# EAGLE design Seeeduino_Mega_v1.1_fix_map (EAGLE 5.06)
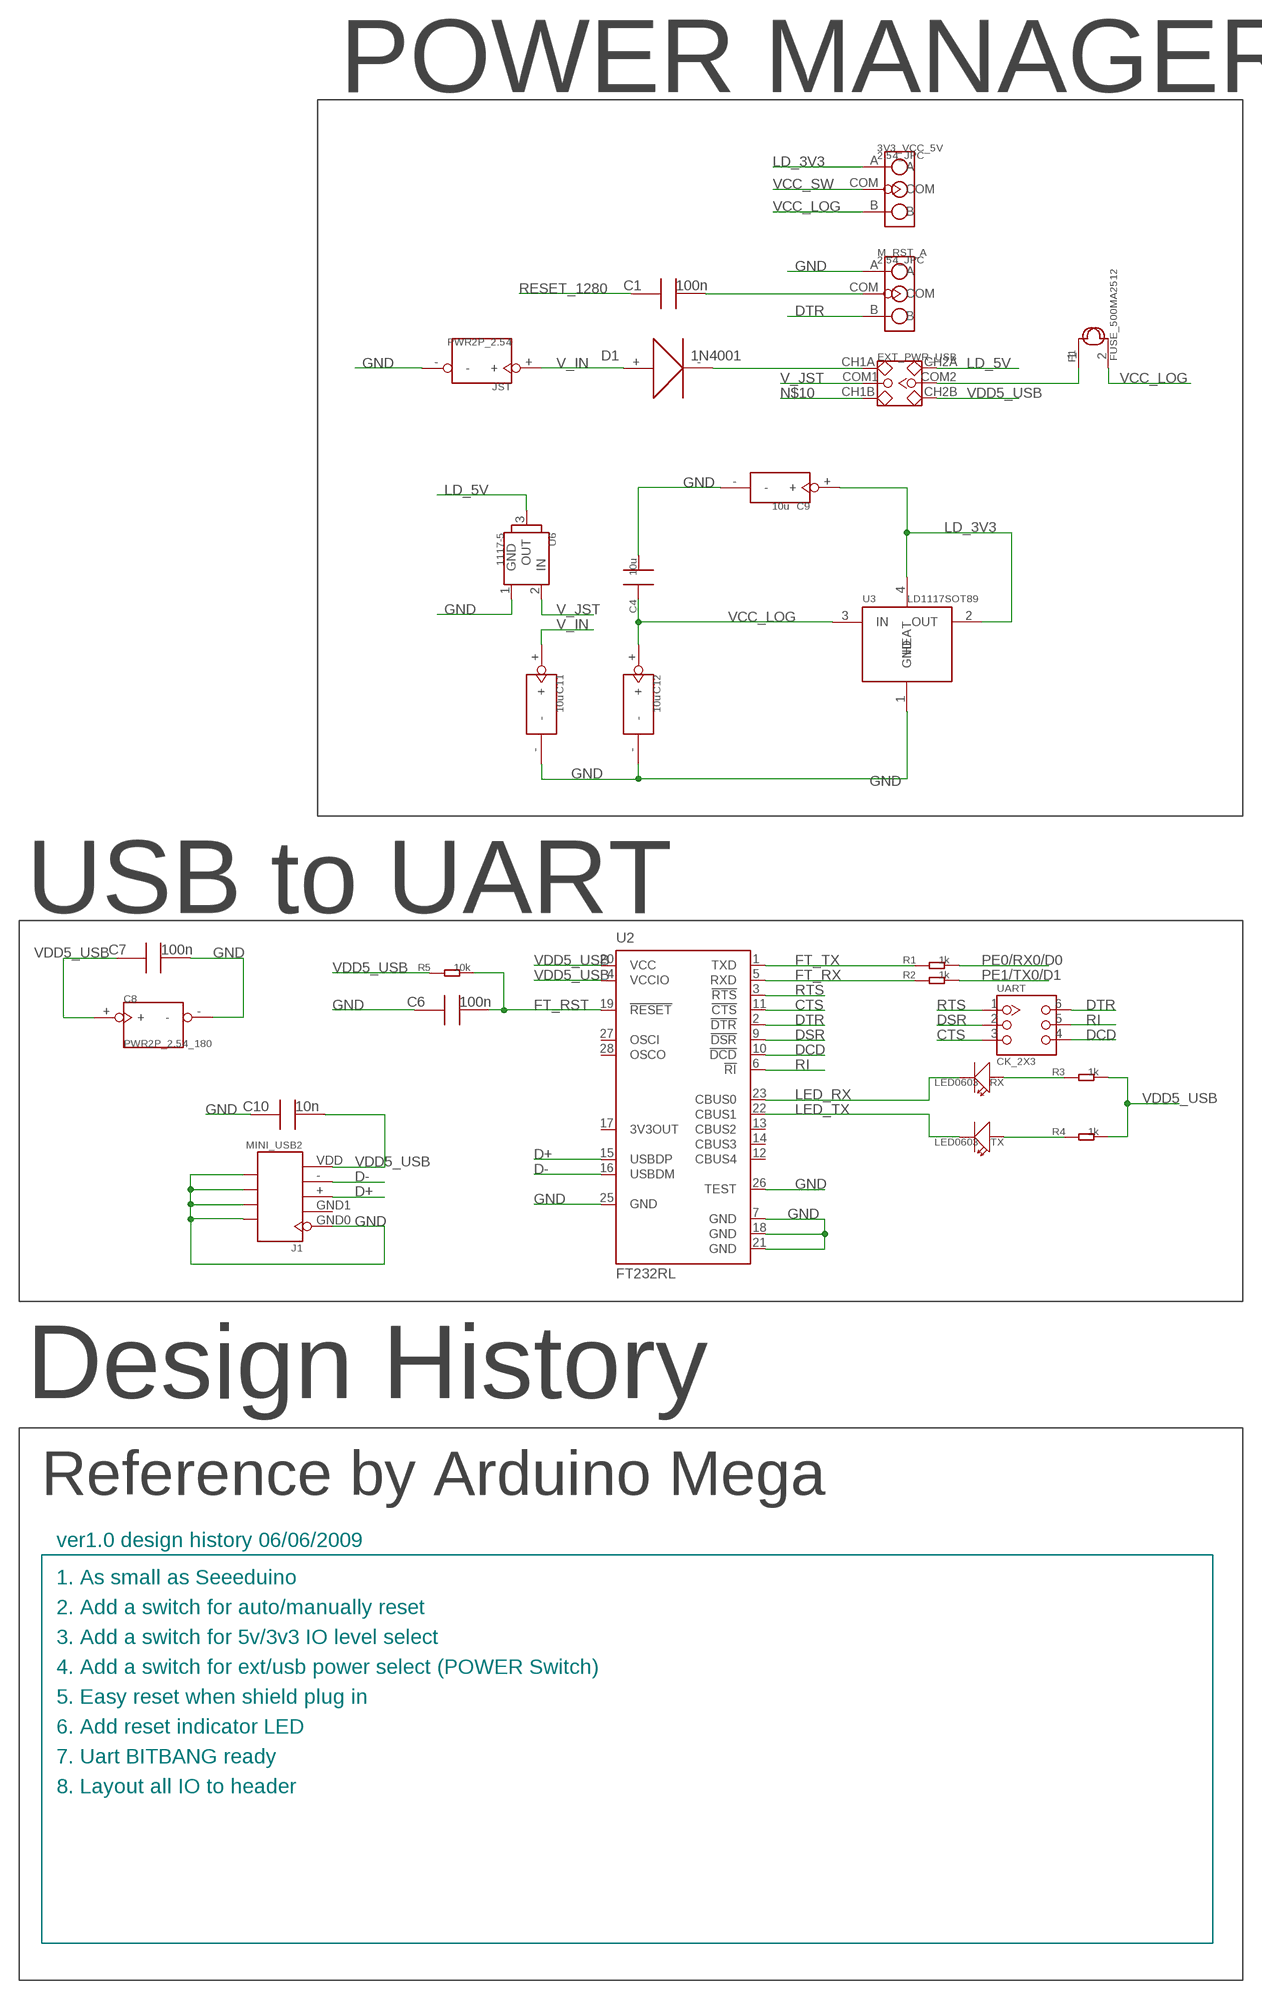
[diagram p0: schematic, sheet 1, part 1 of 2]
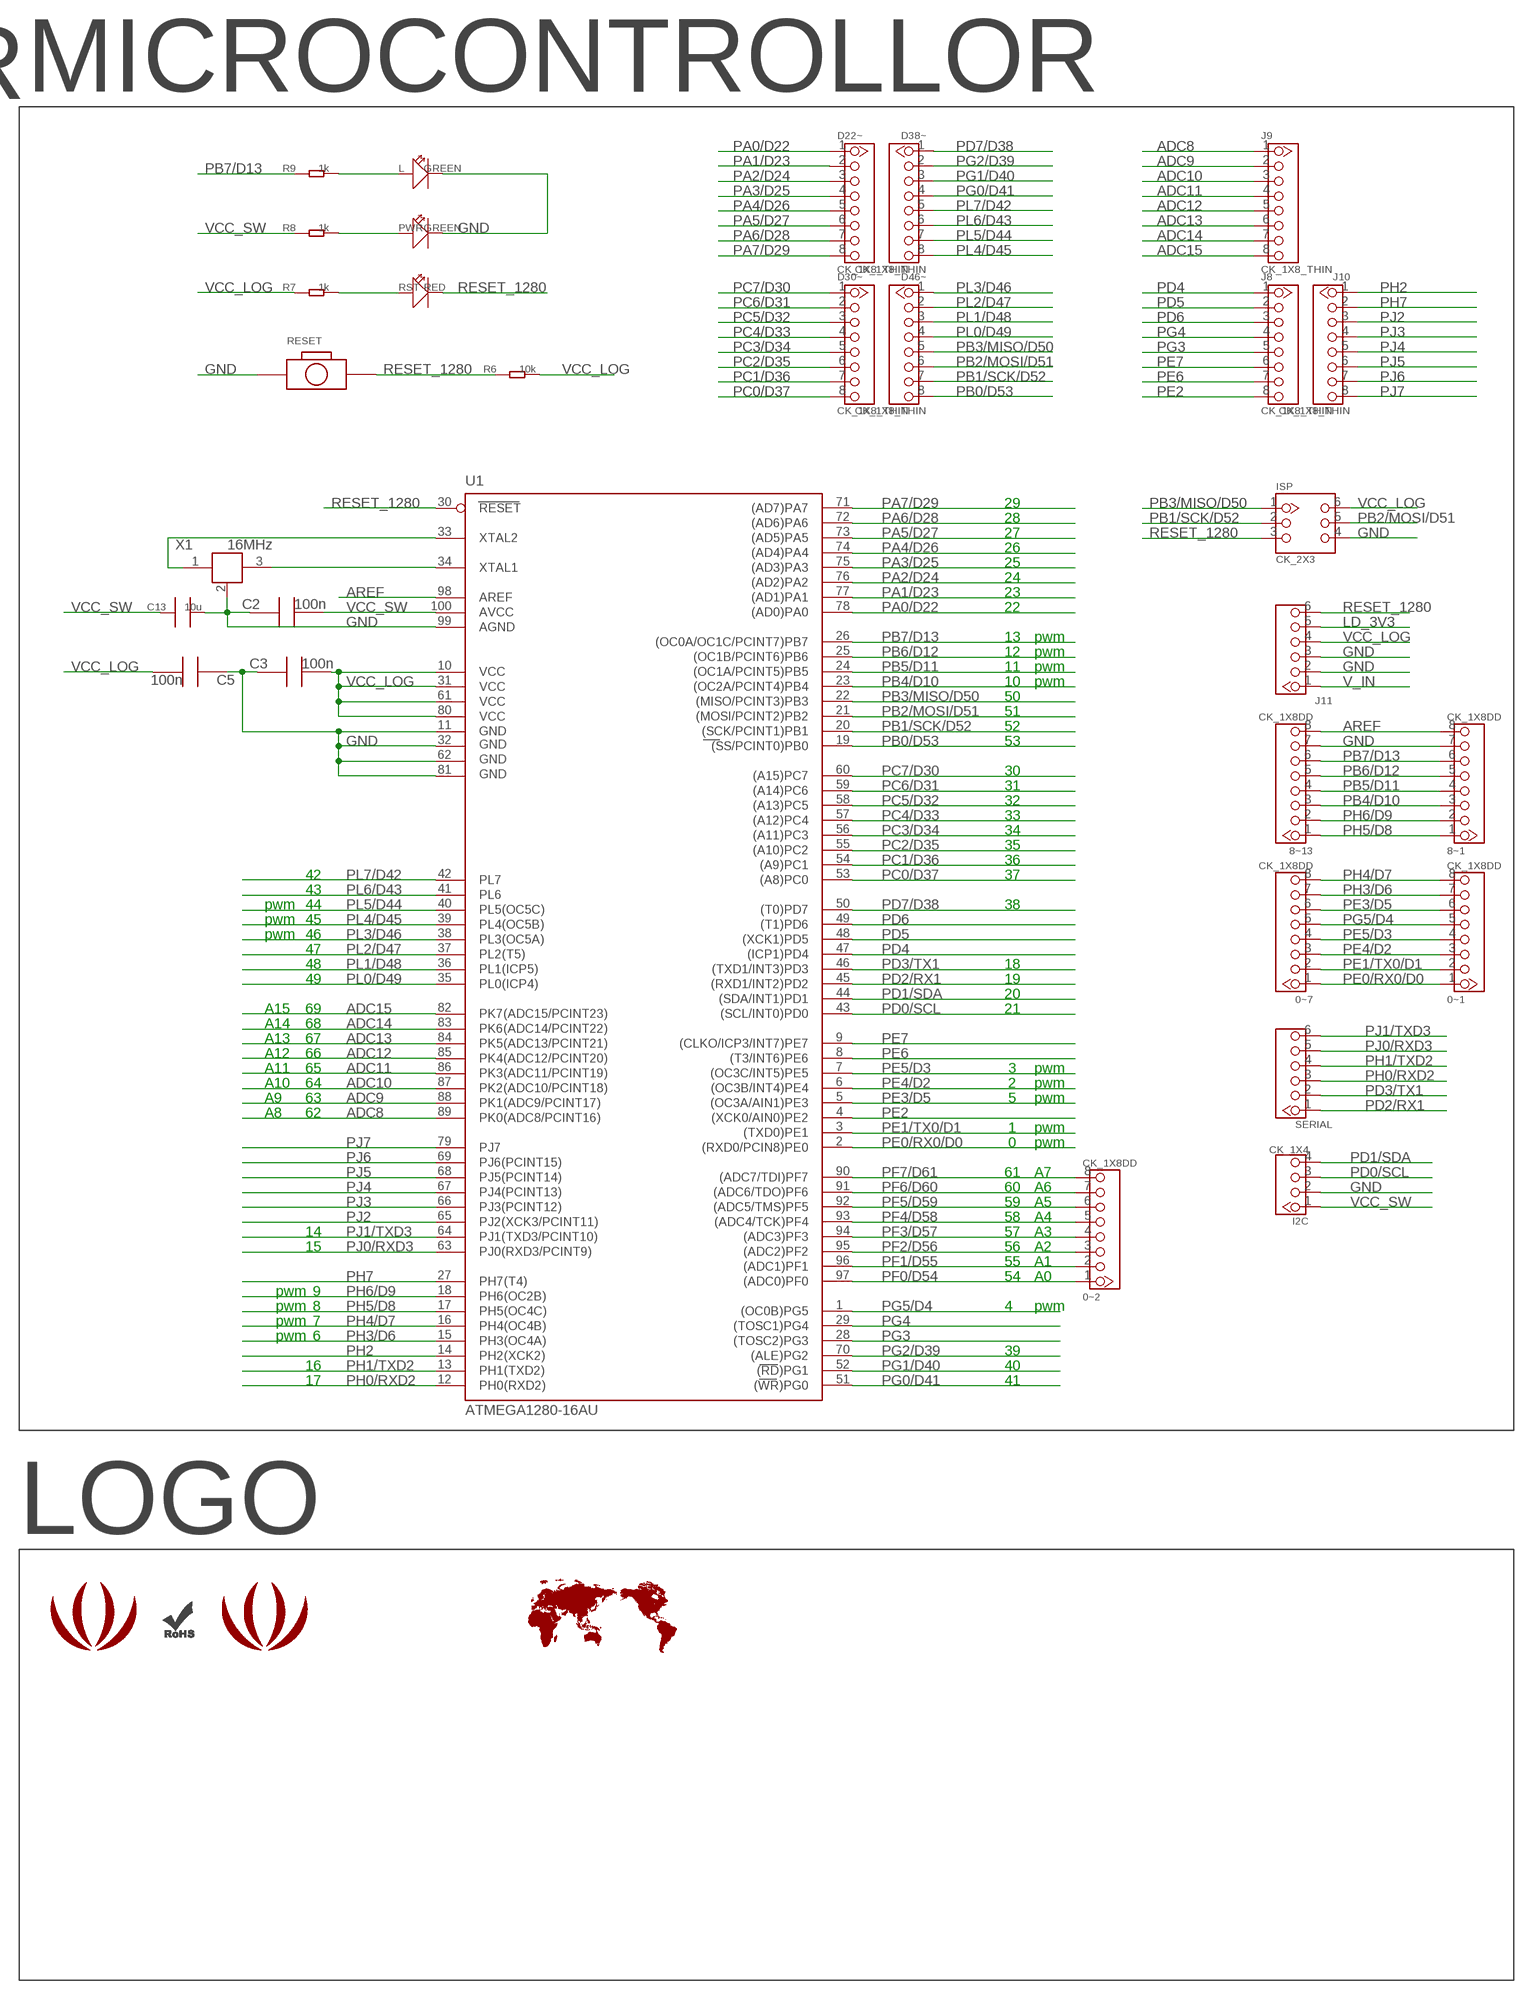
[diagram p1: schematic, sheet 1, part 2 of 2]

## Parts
0~1  CK_1X8DD  [CK_1X8]
0~2  CK_1X8DD  [CK_1X8]
0~7  CK_1X8DD  [CK_1X8]
3V3_VCC_5V  2.54_JPC  [2.54_JP_C]
8~1  CK_1X8DD  [CK_1X8]
8~13  CK_1X8DD  [CK_1X8]
C1  100n  C0603  [0603]
C2  100n  C0603  [0603]
C3  100n  C0603  [0603]
C4  10u  C0805  [0805]
C5  100n  C0603  [0603]
C6  100n  C0603  [0603]
C7  100n  C0603  [0603]
C8  PWR2P_2.54_180  [PWR_1X2]
C9  10u  C_TAN_3X3.5  [C_TAN_3X3.5]
C10  10n  C0603  [0603]
C11  10u  C_TAN_3X3.5  [C_TAN_3X3.5]
C12  10u  C_TAN_3X3.5  [C_TAN_3X3.5]
C13  10u  C0805  [0805]
D1  1N4001  DIODE2010  [DIODE_2010]
D22~  CK_1X8_THIN  [CK_1X8_THIN]
D30~  CK_1X8_THIN  [CK_1X8_THIN]
D38~  CK_1X8_THIN  [CK_1X8_THIN]
D46~  CK_1X8_THIN  [CK_1X8_THIN]
EXT_PWR_USB  2.54SW_2CH  [2.54SW_2CH]
F1  FUSE_500MA2512  [2512]
I2C  CK_1X4  [CK_1X4]
ISP  CK_2X3  [CK_2X3_THIN]
J1  MINI_USB2  [MINI_USB2]
J8  CK_1X8_THIN  [CK_1X8_THIN]
J9  CK_1X8_THIN  [CK_1X8_THIN]
J10  CK_1X8_THIN  [CK_1X8_THIN]
J11  CK_1X6  [CK_1X6]
JST  PWR2P_2.54  [PWR_JST]
L  GREEN  LED0603  [LED0603]
LOGO1  LOGO_SILK  [LOGO_SILK]
LOGO2  ROHSSILK  [ROHS_SILK]
LOGO3  LOGO_COPPER150X124  [LOGO_COPPER_150X124]
M_RST_A  2.54_JPC  [2.54_JP_C]
PWR  GREEN  LED0603  [LED0603]
R1  1k  R0603  [0603]
R2  1k  R0603  [0603]
R3  1k  R0603  [0603]
R4  1k  R0603  [0603]
R5  10k  R0603  [0603]
R6  10k  R0603  [0603]
R7  1k  R0603  [0603]
R8  1k  R0603  [0603]
R9  1k  R0603  [0603]
RESET  BOTTON_1_DP  [BTN_5.0_RST]
RST  RED  LED0603  [LED0603]
RX  LED0603  [LED0603]
SERIAL  CK_1X6  [CK_1X6]
TX  LED0603  [LED0603]
U1  ATMEGA1280-16AU  [TQFP100]
U2  FT232RL  [SSOP28]
U3  LD1117SOT89  [SOT89]
U6  1117-5  [TO252]
U$2  WORLD_MAP_IID  [WORLD_MAP_1000X500]
UART  CK_2X3  [CK_2X3_THIN]
X1  16MHz  XTAL_NC4X3  [XTAL_4X3]

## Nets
ADC8: J9.1 U1.89(PK0(ADC8/PCINT16))
ADC9: J9.2 U1.88(PK1(ADC9/PCINT17))
ADC10: J9.3 U1.87(PK2(ADC10/PCINT18))
ADC11: J9.4 U1.86(PK3(ADC11/PCINT19))
ADC12: J9.5 U1.85(PK4(ADC12/PCINT20))
ADC13: J9.6 U1.84(PK5(ADC13/PCINT21))
ADC14: J9.7 U1.83(PK6(ADC14/PCINT22))
ADC15: J9.8 U1.82(PK7(ADC15/PCINT23))
AREF: 8~1.8 8~13.8 U1.98(AREF)
CTS: U2.11(!CTS) UART.3
D+: J1.+ U2.15(USBDP)
D-: J1.- U2.16(USBDM)
DCD: U2.10(!DCD) UART.4
DSR: U2.9(!DSR) UART.2
DTR: M_RST_A.B U2.2(!DTR) UART.6
FT_RST: C6.2 R5.2 U2.19(!RESET)
FT_RX: R2.1 U2.5(RXD)
FT_TX: R1.1 U2.1(TXD)
GND: 8~1.7 8~13.7 C2.1 C3.1 C4.2 C5.1 C6.1 C7.2 C8.- C9.- C10.1 C11.- C12.- C13.2 I2C.2 ISP.4 J1.GND0 J1.P$6 J1.P$7 J1.P$8 J1.P$9 J11.2 J11.3 JST.- L.2(-) M_RST_A.A PWR.2(-) RESET.P$1 U1.11(GND) U1.32(GND1) U1.62(GND2) U1.81(GND3) U1.99(AGND) U2.7(GND) U2.18(GND) U2.21(GND) U2.25(GND) U2.26(TEST) U3.1(GND) U6.1(GND) X1.2(GND)
LD_3V3: 3V3_VCC_5V.A C9.+ J11.5 U3.2(OUT) U3.4(HEAT)
LD_5V: EXT_PWR_USB.CH2A U6.3(OUT)
LED_RX: RX.2(-) U2.23(CBUS0)
LED_TX: TX.2(-) U2.22(CBUS1)
N$1: EXT_PWR_USB.COM2 F1.1
N$2: U1.34(XTAL1) X1.3
N$3: U1.33(XTAL2) X1.1
N$5: R7.2 RST.1(+)
N$7: D1.- EXT_PWR_USB.CH1A
N$8: PWR.1(+) R8.2
N$9: L.1(+) R9.2
N$10: EXT_PWR_USB.CH1B
N$18: C1.2 M_RST_A.COM
N$31: R3.1 RX.1(+)
N$32: R4.1 TX.1(+)
PA0/D22: D22~.1 U1.78((AD0)PA0)
PA1/D23: D22~.2 U1.77((AD1)PA1)
PA2/D24: D22~.3 U1.76((AD2)PA2)
PA3/D25: D22~.4 U1.75((AD3)PA3)
PA4/D26: D22~.5 U1.74((AD4)PA4)
PA5/D27: D22~.6 U1.73((AD5)PA5)
PA6/D28: D22~.7 U1.72((AD6)PA6)
PA7/D29: D22~.8 U1.71((AD7)PA7)
PB0/D53: D46~.8 U1.19((SS/PCINT0)PB0)
PB1/SCK/D52: D46~.7 ISP.2 U1.20((SCK/PCINT1)PB1)
PB2/MOSI/D51: D46~.6 ISP.5 U1.21((MOSI/PCINT2)PB2)
PB3/MISO/D50: D46~.5 ISP.1 U1.22((MISO/PCINT3)PB3)
PB4/D10: 8~1.3 8~13.3 U1.23((OC2A/PCINT4)PB4)
PB5/D11: 8~1.4 8~13.4 U1.24((OC1A/PCINT5)PB5)
PB6/D12: 8~1.5 8~13.5 U1.25((OC1B/PCINT6)PB6)
PB7/D13: 8~1.6 8~13.6 R9.1 U1.26((OC0A/OC1C/PCINT7)PB7)
PC0/D37: D30~.8 U1.53((A8)PC0)
PC1/D36: D30~.7 U1.54((A9)PC1)
PC2/D35: D30~.6 U1.55((A10)PC2)
PC3/D34: D30~.5 U1.56((A11)PC3)
PC4/D33: D30~.4 U1.57((A12)PC4)
PC5/D32: D30~.3 U1.58((A13)PC5)
PC6/D31: D30~.2 U1.59((A14)PC6)
PC7/D30: D30~.1 U1.60((A15)PC7)
PD0/SCL: I2C.3 U1.43((SCL/INT0)PD0)
PD1/SDA: I2C.4 U1.44((SDA/INT1)PD1)
PD2/RX1: SERIAL.1 U1.45((RXD1/INT2)PD2)
PD3/TX1: SERIAL.2 U1.46((TXD1/INT3)PD3)
PD4: J8.1 U1.47((ICP1)PD4)
PD5: J8.2 U1.48((XCK1)PD5)
PD6: J8.3 U1.49((T1)PD6)
PD7/D38: D38~.1 U1.50((T0)PD7)
PE0/RX0/D0: 0~1.1 0~7.1 R1.2 U1.2((RXD0/PCIN8)PE0)
PE1/TX0/D1: 0~1.2 0~7.2 R2.2 U1.3((TXD0)PE1)
PE2: J8.8 U1.4((XCK0/AIN0)PE2)
PE3/D5: 0~1.6 0~7.6 U1.5((OC3A/AIN1)PE3)
PE4/D2: 0~1.3 0~7.3 U1.6((OC3B/INT4)PE4)
PE5/D3: 0~1.4 0~7.4 U1.7((OC3C/INT5)PE5)
PE6: J8.7 U1.8((T3/INT6)PE6)
PE7: J8.6 U1.9((CLKO/ICP3/INT7)PE7)
PF0/D54: 0~2.1 U1.97((ADC0)PF0)
PF1/D55: 0~2.2 U1.96((ADC1)PF1)
PF2/D56: 0~2.3 U1.95((ADC2)PF2)
PF3/D57: 0~2.4 U1.94((ADC3)PF3)
PF4/D58: 0~2.5 U1.93((ADC4/TCK)PF4)
PF5/D59: 0~2.6 U1.92((ADC5/TMS)PF5)
PF6/D60: 0~2.7 U1.91((ADC6/TDO)PF6)
PF7/D61: 0~2.8 U1.90((ADC7/TDI)PF7)
PG0/D41: D38~.4 U1.51((WR)PG0)
PG1/D40: D38~.3 U1.52((RD)PG1)
PG2/D39: D38~.2 U1.70((ALE)PG2)
PG3: J8.5 U1.28((TOSC2)PG3)
PG4: J8.4 U1.29((TOSC1)PG4)
PG5/D4: 0~1.5 0~7.5 U1.1((OC0B)PG5)
PH0/RXD2: SERIAL.3 U1.12(PH0(RXD2))
PH1/TXD2: SERIAL.4 U1.13(PH1(TXD2))
PH2: J10.1 U1.14(PH2(XCK2))
PH3/D6: 0~1.7 0~7.7 U1.15(PH3(OC4A))
PH4/D7: 0~1.8 0~7.8 U1.16(PH4(OC4B))
PH5/D8: 8~1.1 8~13.1 U1.17(PH5(OC4C))
PH6/D9: 8~1.2 8~13.2 U1.18(PH6(OC2B))
PH7: J10.2 U1.27(PH7(T4))
PJ0/RXD3: SERIAL.5 U1.63(PJ0(RXD3/PCINT9))
PJ1/TXD3: SERIAL.6 U1.64(PJ1(TXD3/PCINT10))
PJ2: J10.3 U1.65(PJ2(XCK3/PCINT11))
PJ3: J10.4 U1.66(PJ3(PCINT12))
PJ4: J10.5 U1.67(PJ4(PCINT13))
PJ5: J10.6 U1.68(PJ5(PCINT14))
PJ6: J10.7 U1.69(PJ6(PCINT15))
PJ7: J10.8 U1.79(PJ7)
PL0/D49: D46~.4 U1.35(PL0(ICP4))
PL1/D48: D46~.3 U1.36(PL1(ICP5))
PL2/D47: D46~.2 U1.37(PL2(T5))
PL3/D46: D46~.1 U1.38(PL3(OC5A))
PL4/D45: D38~.8 U1.39(PL4(OC5B))
PL5/D44: D38~.7 U1.40(PL5(OC5C))
PL6/D43: D38~.6 U1.41(PL6)
PL7/D42: D38~.5 U1.42(PL7)
RESET_1280: C1.1 ISP.3 J11.6 R6.1 RESET.P$2 RST.2(-) U1.30(RESET)
RI: U2.6(!RI) UART.5
RTS: U2.3(!RTS) UART.1
V_IN: C11.+ D1.+ J11.1 JST.+
V_JST: EXT_PWR_USB.COM1 U6.2(IN)
VCC_LOG: 3V3_VCC_5V.B C3.2 C4.1 C5.2 C12.+ F1.2 ISP.6 J11.4 R6.2 R7.1 U1.10(VCC) U1.31(VCC1) U1.61(VCC2) U1.80(VCC3) U3.3(IN)
VCC_SW: 3V3_VCC_5V.COM C2.2 C13.1 I2C.1 R8.1 U1.100(AVCC)
VDD5_USB: C7.1 C8.+ C10.2 EXT_PWR_USB.CH2B J1.VDD R3.2 R4.2 R5.1 U2.4(VCCIO) U2.20(VCC)
Unconnected: J1.GND1 U2.12(CBUS4) U2.13(CBUS2) U2.14(CBUS3) U2.17(3V3OUT) U2.27(OSCI) U2.28(OSCO)

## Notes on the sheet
- POWER MANAGER | MICROCONTROLLOR
- 29
- 28
- 27
- 26
- 25
- 24
- 23
- 22
- 13 | pwm
- 12 | pwm
- 11 | pwm
- 10 | pwm
- 50
- 51
- 52
- 53
- 30
- 31
- 32
- 33
- 34
- 35
- 36
- 42 | 37
- 43
- pwm | 44 | 38
- USB to UART
- pwm | 45
- pwm | 46
- 47
- 48 | 18
- 49 | 19
- 20
- A15 | 69 | 21
- A14 | 68
- A13 | 67
- A12 | 66
- A11 | 65 | 3 | pwm
- A10 | 64 | 2 | pwm
- A9 | 63 | 5 | pwm
- A8 | 62
- 1 | pwm
- 0 | pwm
- 61 | A7
- 60 | A6
- 59 | A5
- 58 | A4
- 14 | 57 | A3
- 15 | 56 | A2
- 55 | A1
- 54 | A0
- pwm | 9
- pwm | 8 | 4 | pwm
- pwm | 7
- pwm | 6
- 39
- 16 | 40
- 17 | 41
- Design History
- Reference by Arduino Mega
- LOGO
- ver1.0 design history 06/06/2009
- 1. As small as Seeeduino
- 2. Add a switch for auto/manually reset
- 3. Add a switch for 5v/3v3 IO level select
- 4. Add a switch for ext/usb power select (POWER Switch)
- 5. Easy reset when shield plug in
- 6. Add reset indicator LED
- 7. Uart BITBANG ready
- 8. Layout all IO to header

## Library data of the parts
0~1 0~2 0~7 8~1 8~13 D22~ D30~ D38~ D46~ J8-J10 = CONNECTER:CK_1X8
3V3_VCC_5V M_RST_A = CPT_CJ:2.54_JP
C1-C3 C5-C7 C10 = CPT_SMD:C0603; C0603: 100N
C4 C13 = CPT_SMD:C0805
C8 JST = CONNECTER:PWR2P_2.54
C9 C11 C12 = CPT_SMD:C_TAN
D1 = CPT_SMD:DIODE
EXT_PWR_USB = CPT_CJ:2.54SW_2CH
F1 = CPT_SMD:FUSE_500MA
I2C = CONNECTER:CK_1X4
ISP UART = CONNECTER:CK_2X3
J1 = CONNECTER:MINI_USB2
J11 SERIAL = CONNECTER:CK_1X6
L PWR RST RX TX = CPT_SMD:LED0603
LOGO1 = logo:LOGO_SILK
LOGO2 = logo:ROHS
LOGO3 = logo:LOGO_COPPER
R1-R9 = CPT_SMD:R0603
RESET = CPT_SMD:BOTTON_1
U1 = ICs_v54:ATMEGA*: MICROCONTROLLER 64/128/256 Kbytes FLASH 4 Kbytes EEPROM 8 Kbytes SRAM 86 General Purpose I/O pins 12-channels16-bit PWM 4 x Serial USARTs 16-channels 10-bit A/D
U2 = ICs_v54:FT232R: Source: http://www.ftdichip.com/Documents/DataSheets/DS_FT232R_v104.pdf
U3 = ICs_v54:LD1117
U6 = ICs_v54:1117-5
U$2 = logo:WORLD_MAP
X1 = CPT_SMD:XTAL_NC

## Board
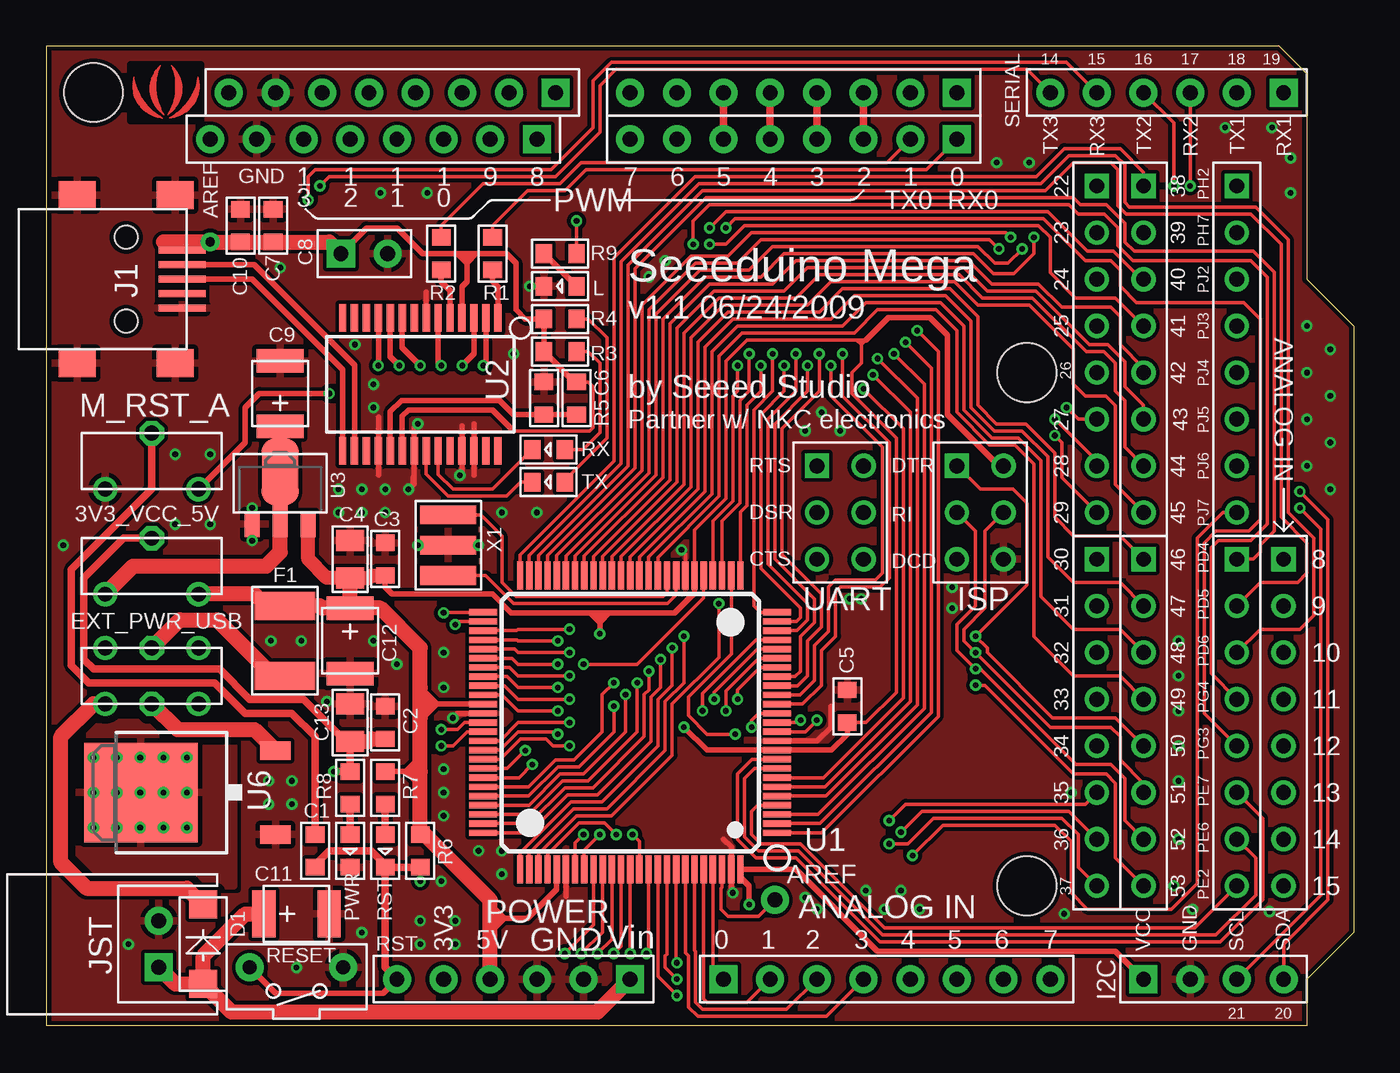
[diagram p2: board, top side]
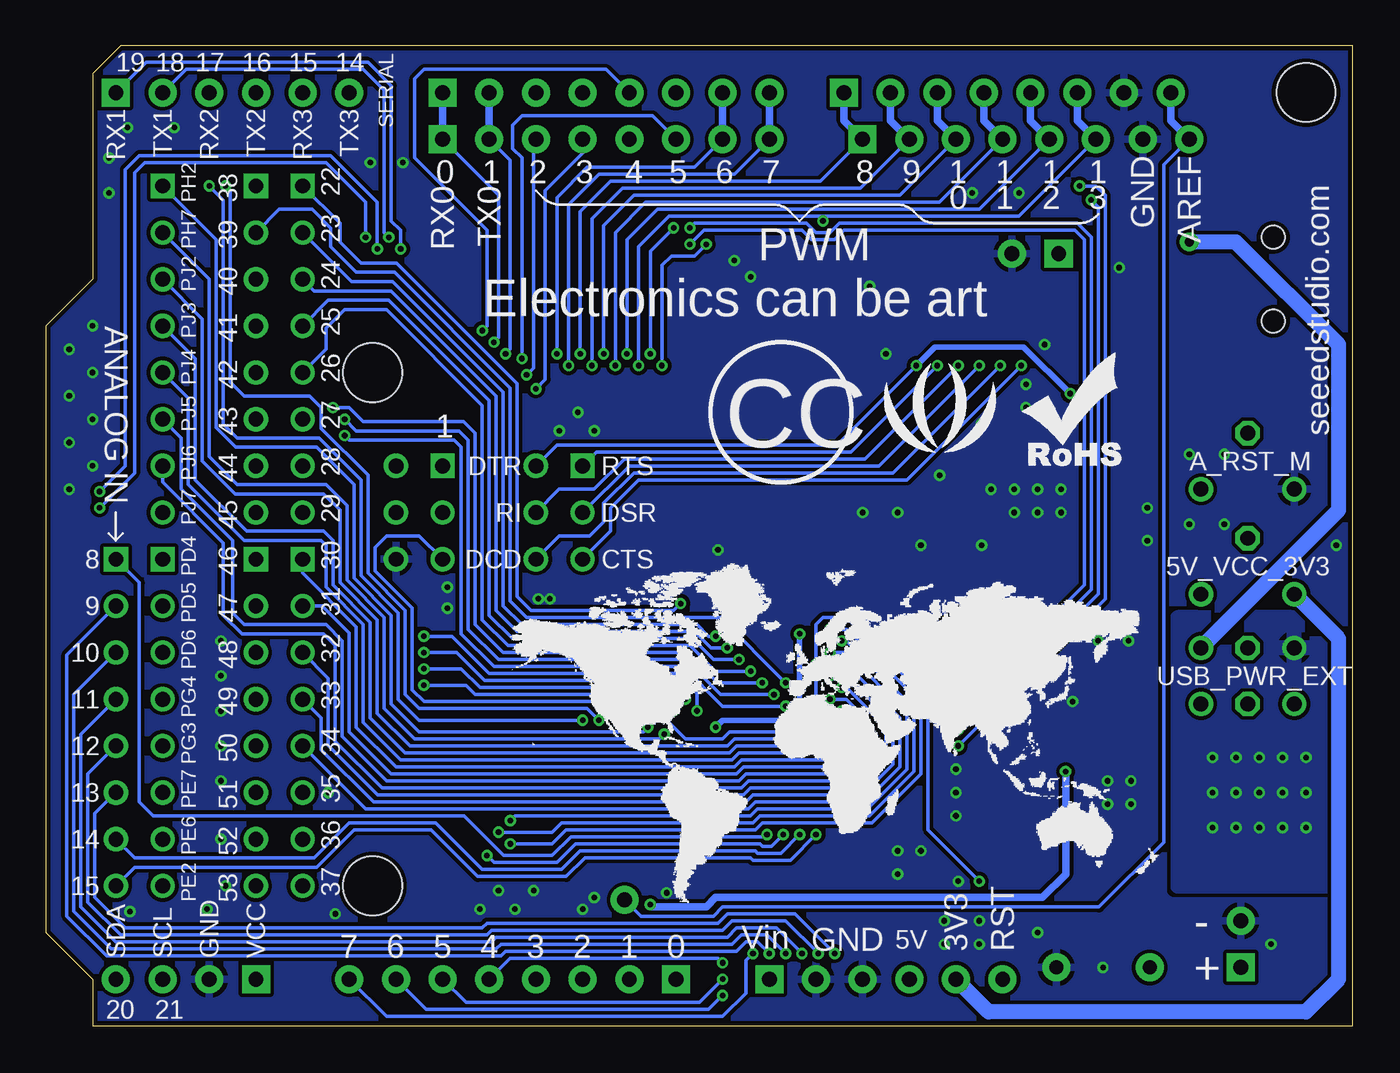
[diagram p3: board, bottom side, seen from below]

Size 71.12 x 53.34 mm. Coordinates in mm from the lower left corner, seen from the top.
Outline: 68.58,40.64 71.12,38.1 71.12,5.08 68.58,2.54 68.58,0 0,0 0,53.34 67.06,53.34 68.58,51.82 68.58,40.64
Copper layers (1*16): Top 0.035mm / dielectric 1.5mm / Bottom 0.035mm
Design rules "rule_manufacture *": minimum track width 8mil, minimum drill 12mil, track to track 6mil, track to pad 6mil, pad to pad 6mil, via to via 8mil, smd to smd 0mil, copper to edge 10mil, drill to drill 10mil, minimum pad ring 10mil, minimum via ring 6mil, stop-mask expansion 2mil, vias tented up to drill 25mil, thermal gap 10mil
Holes 3.2 mm at 2.54,50.8 2.54,50.8 53.34,7.62 53.34,35.56
tRestrict: area 22.5,30.6 to 23.4,32; area 17.3,30.6 to 18.2,32; area 19.3,30.6 to 20.7,32; area 4.6,49.3 to 8.4,52.3; area 20.1,37.8 to 21.2,39.2

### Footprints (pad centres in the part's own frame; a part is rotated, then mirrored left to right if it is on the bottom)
CK_1X8 = drill 0.813 pad 1.524 square: 1 0,8.89 | drill 0.813 pad 1.524 round: 2 0,6.35; 3 0,3.81; 4 0,1.27; 5 0,-1.27; 6 0,-3.81; 7 0,-6.35; 8 0,-8.89
2.54_JP_C = drill 0.813 round: A -1.27,2.54; B -1.27,-2.54 | drill 0.813 octagon: COM 1.778,0
0603 = smd 0.889 x 1.016: 1 -0.889,0; 2 0.889,0
0805 = smd 1.143 x 1.524: 1 -1.016,0; 2 1.016,0
PWR_1X2 = drill 0.813 pad 1.524 square: + 1.27,0 | drill 0.813 pad 1.524 round: - -1.27,0
C_TAN_3X3.5 = smd 2.54 x 1.27: + 0,1.778; - 0,-1.778
DIODE_2010 = smd 1.524 x 1.524: + 0,-2.159; - 0,2.159
CK_1X8_THIN = drill 0.813 pad 1.27 square: 1 0,8.89 | drill 0.813 pad 1.27 round: 2 0,6.35; 3 0,3.81; 4 0,1.27; 5 0,-1.27; 6 0,-3.81; 7 0,-6.35; 8 0,-8.89
2.54SW_2CH = drill 0.813 pad 1.27 round: CH1A -1.524,2.54; CH1B -1.524,-2.54; CH2A 1.524,2.54; CH2B 1.524,-2.54 | drill 0.813 pad 1.27 octagon: COM1 -1.524,0; COM2 1.524,0
2512 = smd 1.524 x 3.302: 1 -1.905,0; 2 1.905,0
CK_1X4 = drill 0.813 pad 1.524 square: 1 0,3.81 | drill 0.813 pad 1.524 round: 2 0,1.27; 3 0,-1.27; 4 0,-3.81
CK_2X3_THIN = drill 0.813 pad 1.27 square: 1 -1.27,2.54 | drill 0.813 pad 1.27 round: 2 -1.27,0; 3 -1.27,-2.54; 4 1.27,-2.54; 5 1.27,0; 6 1.27,2.54
MINI_USB2 = smd 2.54 x 0.381: + -2.286,0; - -2.286,-0.787; GND0 -2.286,1.575; GND1 -2.286,0.787; VDD -2.286,-1.575 | smd 2.032 x 1.524: P$6 -1.905,4.572; P$7 -1.905,-4.572; P$8 3.429,4.572; P$9 3.429,-4.572 | hole 1.27: 0.762,2.286; 0.762,-2.286
CK_1X6 = drill 0.813 pad 1.524 square: 1 0,6.35 | drill 0.813 pad 1.524 round: 2 0,3.81; 3 0,1.27; 4 0,-1.27; 5 0,-3.81; 6 0,-6.35
PWR_JST = drill 0.813 pad 1.524 square: + 0,-1.27 | drill 0.813 pad 1.524 round: - 0,1.27
LED0603 = smd 0.889 x 1.016: 1 -0.889,0; 2 0.889,0
BTN_5.0_RST = drill 0.762 pad 1.524 round: P$1 0,2.54; P$2 0,-2.54
TQFP100 = smd 1.524 x 0.343: 1 -8,6; 2 -8,5.5; 3 -8,5; 4 -8,4.5; 5 -8,4; 6 -8,3.5; 7 -8,3; 8 -8,2.5; 9 -8,2; 10 -8,1.5; 11 -8,1; 12 -8,0.5; 13 -8,0; 14 -8,-0.5; 15 -8,-1; 16 -8,-1.5; 17 -8,-2; 18 -8,-2.5; 19 -8,-3; 20 -8,-3.5; 21 -8,-4; 22 -8,-4.5; 23 -8,-5; 24 -8,-5.5; 25 -8,-6; 51 8,-6; 52 8,-5.5; 53 8,-5; 54 8,-4.5; 55 8,-4; 56 8,-3.5; 57 8,-3; 58 8,-2.5; 59 8,-2; 60 8,-1.5; 61 8,-1; 62 8,-0.5; 63 8,0; 64 8,0.5; 65 8,1; 66 8,1.5; 67 8,2; 68 8,2.5; 69 8,3; 70 8,3.5; 71 8,4; 72 8,4.5; 73 8,5; 74 8,5.5; 75 8,6 | smd 0.343 x 1.524: 26 -6,-8; 27 -5.5,-8; 28 -5,-8; 29 -4.5,-8; 30 -4,-8; 31 -3.5,-8; 32 -3,-8; 33 -2.5,-8; 34 -2,-8; 35 -1.5,-8; 36 -1,-8; 37 -0.5,-8; 38 0,-8; 39 0.5,-8; 40 1,-8; 41 1.5,-8; 42 2,-8; 43 2.5,-8; 44 3,-8; 45 3.5,-8; 46 4,-8; 47 4.5,-8; 48 5,-8; 49 5.5,-8; 50 6,-8; 76 6,8; 77 5.5,8; 78 5,8; 79 4.5,8; 80 4,8; 81 3.5,8; 82 3,8; 83 2.5,8; 84 2,8; 85 1.5,8; 86 1,8; 87 0.5,8; 88 0,8; 89 -0.5,8; 90 -1,8; 91 -1.5,8; 92 -2,8; 93 -2.5,8; 94 -3,8; 95 -3.5,8; 96 -4,8; 97 -4.5,8; 98 -5,8; 99 -5.5,8; 100 -6,8
SSOP28 = smd 0.4 x 1.5: 1 -4.225,-3.625; 2 -3.575,-3.625; 3 -2.925,-3.625; 4 -2.275,-3.625; 5 -1.625,-3.625; 6 -0.975,-3.625; 7 -0.325,-3.625; 8 0.325,-3.625; 9 0.975,-3.625; 10 1.625,-3.625; 11 2.275,-3.625; 12 2.925,-3.625; 13 3.575,-3.625; 14 4.225,-3.625; 15 4.225,3.625; 16 3.575,3.625; 17 2.925,3.625; 18 2.275,3.625; 19 1.625,3.625; 20 0.975,3.625; 21 0.325,3.625; 22 -0.325,3.625; 23 -0.975,3.625; 24 -1.625,3.625; 25 -2.275,3.625; 26 -2.925,3.625; 27 -3.575,3.625; 28 -4.225,3.625
SOT89 = smd 0.8 x 1.4: 1 -1.524,-1.905; 3 1.524,-1.905 | smd 0.8 x 1.9: 2 0,-1.651 | smd 2.032 x 3.65: 4 0,0.94
TO252 = smd 1.016 x 1.651: 1 -2.286,-4.826; 2 2.286,-4.826 | smd 5.4 x 6.2: 3 0,2.5
XTAL_4X3 = smd 1.016 x 3.048: 1 -1.651,0; 2 0,0; 3 1.651,0

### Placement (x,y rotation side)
0~1  40.64,48.26 270 top
0~2  45.72,2.54 90 top
0~7  40.64,50.8 270 top
3V3_VCC_5V  5.71,24.77 90 top
8~1  17.78,48.26 270 top
8~13  18.8,50.8 270 top
C1  14.61,9.53 90 top
C2  18.41,16.51 270 top
C3  18.41,25.4 270 top
C4  16.51,25.4 90 top
C5  43.56,17.4 270 top
C6  27.05,34.16 270 top
C7  12.32,43.56 90 top
C8  17.27,42.04 180 top
C9  12.7,34.42 180 top
C10  10.54,43.56 270 top
C11  13.59,6.1 90 top
C12  16.51,20.95 0 top
C13  16.51,16.51 90 top
D1  8.51,4.45 0 top
D22~  57.15,36.83 0 top
D30~  57.15,16.51 0 top
D38~  59.69,36.83 0 top
D46~  59.69,16.51 0 top
EXT_PWR_USB  5.71,19.05 90 top
F1  12.95,20.95 90 top
I2C  63.5,2.54 90 top
ISP  50.8,27.94 0 top
J1  5.08,40.64 180 top
J8  64.77,16.51 0 top
J9  67.31,16.51 0 top
J10  64.77,36.83 0 top
J11  25.4,2.54 270 top
JST  6.1,4.45 0 top
L  27.94,40.26 180 top
LOGO1  22.48,32.89 0 bottom
LOGO2  15.88,32.89 0 bottom
LOGO3  6.48,50.55 0 top
M_RST_A  5.71,30.48 90 top
PWR  16.51,9.53 270 top
R1  24.26,42.04 90 top
R2  21.46,42.04 90 top
R3  27.94,36.7 180 top
R4  27.94,38.48 180 top
R5  28.83,34.16 270 top
R6  20.32,9.53 90 top
R7  18.41,12.95 270 top
R8  16.51,12.95 270 top
R9  27.94,42.04 180 top
RESET  13.59,3.17 270 top
RST  18.41,9.53 270 top
RX  27.3,31.37 180 top
SERIAL  60.96,50.8 270 top
TX  27.3,29.59 180 top
U1  31.75,16.51 180 top
U2  20.32,34.92 180 top
U3  12.7,29.21 0 top
U6  7.62,12.7 90 top
U$2  18.41,16.38 0 bottom
UART  43.18,27.94 0 top
X1  21.84,26.16 90 top

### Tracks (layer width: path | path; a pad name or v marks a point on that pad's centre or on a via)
ADC8  (via drill 0.3)
  Top 0.203: U1.89 32.25,10.04 v31.88,10.41
  Bottom 0.203: J9.1 66.04,24.13 66.04,12.19 65.28,11.43 48.36,11.43 46.2,9.27 43.56,9.27 42.55,10.29 32,10.29 v31.88,10.41
ADC9  (via drill 0.3)
  Top 0.203: v31.75,3.94 U1.88
  Bottom 0.203: v31.75,3.94 32.38,4.57 33.02,4.57 33.53,4.06 46.1,4.06 46.35,3.81 67.82,3.81 69.98,5.97 69.98,20.19 J9.2
ADC10  (via drill 0.3)
  Top 0.203: U1.87 31.25,4.33 v30.86,3.94
  Bottom 0.203: v30.86,3.94 31.88,4.95 33.27,4.95 33.78,4.45 46.35,4.45 46.61,4.19 67.56,4.19 69.6,6.22 69.6,18.03 J9.3
ADC11  (via drill 0.3)
  Top 0.203: U1.86 30.75,4.71 v29.97,3.94
  Bottom 0.203: v29.97,3.94 31.37,5.33 33.53,5.33 34.04,4.83 46.61,4.83 46.86,4.57 67.31,4.57 69.22,6.48 69.22,15.88 J9.4
ADC12  (via drill 0.3)
  Top 0.203: U1.85 30.25,5.1 v29.08,3.94
  Bottom 0.203: v29.08,3.94 30.86,5.71 33.78,5.71 34.29,5.21 46.86,5.21 47.12,4.95 67.06,4.95 68.83,6.73 68.83,13.72 J9.5
ADC13  (via drill 0.3)
  Top 0.203: U1.84 29.75,5.49 v28.19,3.94
  Bottom 0.203: v28.19,3.94 30.35,6.1 34.04,6.1 34.54,5.59 47.12,5.59 47.37,5.33 66.8,5.33 68.45,6.99 68.45,11.56 J9.6
ADC14  (via drill 0.3)
  Top 0.203: U1.83 29.25,9.56 v30.1,10.41
  Bottom 0.203: J9.7 66.29,9.14 56.52,9.14 54.61,11.05 49.91,11.05 47.37,8.51 43.05,8.51 42.04,9.53 32.51,9.53 32.38,9.4 31.11,9.4 v30.1,10.41
ADC15  (via drill 0.3)
  Top 0.203: U1.82 28.75,9.95 v29.21,10.41
  Bottom 0.203: J9.8 66.29,8.64 56.39,8.64 54.36,10.67 50.16,10.67 47.62,8.13 42.8,8.13 41.78,9.14 32.77,9.14 32.64,9.02 30.61,9.02 v29.21,10.41
AREF  (via drill 0.81 pad 1.52)
  Top 0.203: U1.98 36.75,7.54 36.7,7.49 36.7,6.35 37.08,5.97 38.73,5.97 v39.62,6.86
  Bottom 0.203: 8~1.8 10.29,46.86 10.29,9.99 13.8,6.48 34.29,6.48 34.8,5.97 38.73,5.97 v39.62,6.86
  Bottom 0.406: 8~1.8 9.91,49.28 8~13.8
CTS  (via drill 0.3)
  Top 0.305: U2.11 18.05,35.95 v18.03,35.94
  Bottom 0.203: v18.03,35.94 24.26,29.72 38.86,29.72 40.39,28.19 40.39,26.92 UART.3
D+
  Top 0.305: J1.+ 11.18,40.64 16.09,35.72 U2.15
D-
  Top 0.305: J1.- 11.28,41.43 16.75,35.96 U2.16
DCD  (via drill 0.3)
  Top 0.305: U2.10 18.7,36.42 v19.18,35.94
  Bottom 0.203: v19.18,35.94 25.02,30.1 39.12,30.1 40.77,28.45 40.77,27.43 41.53,26.67 43.18,26.67 UART.4
DSR  (via drill 0.3)
  Top 0.305: U2.9 19.34,36.92 v20.32,35.94
  Bottom 0.203: v20.32,35.94 25.78,30.48 39.37,30.48 UART.2
DTR  (via drill 0.3)
  Top 0.305: U2.2 23.89,36.09 v23.75,35.94 | M_RST_A.B 10.79,31.75 10.79,33.66 11.56,34.42 v15.37,34.42
  Bottom 0.203: v23.75,35.94 28.07,31.62 43.31,31.62 UART.6
  Bottom 0.305: v23.75,35.94 22.73,36.96 17.91,36.96 v15.37,34.42
FT_RST
  Top 0.305: R5.2 C6.2 25.4,33.27 24.64,34.04 19.3,34.04 18.7,33.43 U2.19
FT_RX
  Top 0.305: U2.5 21.95,40.03 21.46,40.51 R2.1
FT_TX
  Top 0.305: U2.1 24.55,40.23 24.26,40.51 R1.1
GND  (via drill 0.3)
  Top 0.203: U1.32 34.75,25.7 v34.54,25.91
  Top 0.305: 18.05,33.14 U2.18 18.05,29.98 | 28.25,7.04 U1.81 | 23.24,29.97 23.25,29.98 23.24,29.98 23.24,32.77 23.25,32.76 U2.26 | U2.25 22.59,32.63 22.61,32.64 22.61,30.1 v22.48,29.97 | U1.62 22.34,17.01 v22.1,16.76 | 36.83,10.16 37.25,9.74 U1.99 37.25,7.33 v37.34,7.24 | U1.11 41.93,15.51 42.67,16.26 42.67,17.4 | 20,29.9 19.94,29.84 19.94,29.46 v19.68,29.21 20,29.52 U2.21 20,32.57 v20.19,32.77 | U2.7 20.64,39.93
  other vias: 11.18,28.19 11.18,26.42 23.5,26.16 20.19,26.16 17.78,34.92 12.19,20.95 18.41,29.21 12.06,13.34 13.34,13.34 13.34,12.06 15.24,17.65 25.4,36.58 26.29,40.26 41.27,6.99 55.37,6.1 44.58,7.37 45.59,6.35 46.48,7.37 47.5,6.35 62.36,6.35 66.55,6.22 13.84,20.95 23.5,9.53 21.46,7.87 22.23,5.71 49.28,23.88 49.28,22.73 41.91,6.35 17.14,29.21 15.88,29.21 15.88,27.94 17.14,27.94 18.41,27.94 21.59,18.41 21.59,20.32 17.78,20.95 12.06,12.06 4.45,4.45 13.59,3.17 17.14,5.08 20.32,5.71 20.32,4.45 22.23,4.45 24.77,9.53 24.77,8.26 21.59,13.97 21.59,12.7 21.59,11.43 19.05,19.68 8.89,27.3 6.99,27.3 6.99,31.11 8.89,31.11 16.76,37.08 17.78,33.66 12.7,41.27 18.16,45.34 20.7,45.34 66.67,48.9 64.14,48.9 61.59,20.95 61.59,19.05 61.59,17.14 61.59,15.24 61.59,13.34 61.59,10.16 67.69,47.24 67.69,45.34 69.85,36.83 68.58,38.1 68.58,35.56 68.58,33.02 68.58,30.48 69.85,34.29 69.85,31.75 69.85,29.21 24.77,27.94 26.67,27.94 41.27,32.38 43.18,32.38 42.16,33.4 32.77,40.77 33.66,41.66 53.47,46.99 51.69,46.99 0.89,26.16 55.75,12.7 61.34,7.62 43.69,23.24 44.32,23.24
  pour Top: -7.62,53.34 -5.08,53.34 -5.08,51.44 -7.62,51.44
  pour Bottom (isolate 0.203, rank 6): 0,53.34 67.03,53.34 68.58,51.79 68.58,40.64 71.12,38.1 71.12,5.08 68.58,2.54 68.58,0 0,0
  pour Top (isolate 0.203, rank 6): 0,53.34 67.03,53.34 68.58,51.79 68.58,40.64 71.12,38.1 71.12,5.08 68.58,2.54 68.58,0 0,0
LD_3V3
  Top 0.813: C9.+ U3.4 U3.2 12.7,25.78 11.94,25.02 4.7,25.02 3V3_VCC_5V.A
  Bottom 0.813: J11.5 19.81,0.76 2.54,0.76 0.76,2.54 0.76,21.08 3V3_VCC_5V.A
LD_5V  (via drill 0.3)
  Top 0.203: U6.3 v5.08,12.7
  other vias: 2.54,14.61 3.81,14.61 5.08,14.61 6.35,14.61 2.54,12.7 3.81,12.7 6.35,12.7 7.62,12.7 5.08,10.79 2.54,10.79 6.35,10.79 7.62,10.79 7.62,14.61 3.81,10.79
  pour Bottom (isolate 0.203): 0,7.62 0,19.69 2.53,22.23 9.53,22.23 9.53,7.62
  pour Top (isolate 0.406): 10.16,16.51 10.16,7.62 2.71,7.62 1.27,9.06 1.27,15.52 2.26,16.51
LED_RX
  Top 0.203: U2.23 21.3,30.01 22.1,29.21 24.26,29.21 RX.2
LED_TX
  Top 0.203: U2.22 20.64,30.03 21.84,28.83 25.02,28.83 25.78,29.59 TX.2
N$1
  Top 0.813: F1.1 12.32,19.05 9.27,22.1 7.24,22.1 EXT_PWR_USB.COM2
N$2
  Top 0.203: U1.34 33.75,23.59 33.53,23.37 25.53,23.37 24.77,24.13 24.77,26.67 23.62,27.81 X1.3
N$3
  Top 0.203: U1.33 34.25,23.45 33.78,22.99 25.4,22.99 23.88,24.51 X1.1
N$5
  Top 0.406: R7.2 RST.1
N$7
  Top 0.813: EXT_PWR_USB.CH1A 2.54,17.53 0.76,15.75 0.76,8.89 2.16,7.49 7.62,7.49 D1.-
N$8
  Top 0.406: R8.2 PWR.1
N$9
  Top 0.305: R9.2 L.1
N$18
  Top 0.406: M_RST_A.COM 5.71,29.21 1.34,24.83 1.34,19.62 2.29,18.67 9.14,18.67 10.79,17.02 13.34,17.02 14.61,15.75 C1.2
N$31
  Top 0.203: R3.1 29.46,36.7 30.1,36.07 30.1,32.28 29.18,31.37 RX.1
N$32
  Top 0.203: R4.1 29.46,38.48 30.48,37.47 30.48,32 28.19,29.72 TX.1
PA0/D22  (via drill 0.3)
  Top 0.203: U1.78 26.75,9.36 28.82,11.43 30.73,11.43 34.04,14.73 34.04,17.53 36.58,20.07 v36.58,22.99
  Bottom 0.203: D22~.1 55.12,43.69 55.12,42.67 53.98,41.53 52.05,41.53 45.47,34.95 45.47,23.37 44.7,22.61 36.96,22.61 v36.58,22.99
PA1/D23  (via drill 0.3)
  Top 0.203: U1.77 26.25,9.39 28.67,11.81 30.48,11.81 33.66,14.99 33.66,17.65 34.67,18.67 v34.67,21.21
  Bottom 0.203: D22~.2 54.48,40.51 52.25,40.51 46.23,34.49 46.23,22.86 45.21,21.84 35.69,21.84 35.05,21.21 v34.67,21.21
PA2/D24  (via drill 0.3)
  Top 0.203: U1.76 25.75,9.42 28.53,12.19 30.23,12.19 33.27,15.24 33.27,17.78 34.04,18.54 v34.04,20.57
  Bottom 0.203: v34.04,20.57 34.92,20.57 35.81,21.46 45.47,21.46 46.61,22.61 46.61,34.27 52.35,40.01 56.52,40.01 D22~.3
PA3/D25  (via drill 0.3)
  Top 0.203: U1.75 26.28,10.51 28.35,12.57 29.97,12.57 32.89,15.49 32.89,17.91 33.4,18.41 v33.4,19.94
  Bottom 0.203: v33.4,19.94 34.8,19.94 35.94,21.08 45.72,21.08 46.99,22.35 46.99,34.03 52.46,39.5 55.75,39.5 D22~.4
PA4/D26  (via drill 0.3)
  Top 0.203: U1.74 26.25,11.01 28.19,12.95 29.72,12.95 32.51,15.75 32.51,18.03 32.77,18.29 v32.77,19.3
  Bottom 0.203: v32.77,19.3 34.67,19.3 36.07,20.7 45.97,20.7 47.37,22.1 47.37,33.78 52.58,38.99 54.86,38.99 55.88,37.97 55.88,36.83 D22~.5
PA5/D27  (via drill 0.3)
  Top 0.203: U1.73 26.24,11.51 28.07,13.34 29.46,13.34 32.13,16 v32.13,18.67 | D22~.6 56.13,33.02 v55.5,33.66
  Bottom 0.203: v32.13,18.67 34.54,18.67 36.2,20.32 46.23,20.32 47.75,21.84 47.75,32.26 48.39,32.89 53.85,32.89 54.61,33.66 v55.5,33.66
PA6/D28  (via drill 0.3)
  Top 0.203: U1.72 26.23,12.01 27.94,13.72 29.21,13.72 31.5,16 v31.5,18.03 | v54.86,33.02 57.15,30.73 D22~.7
  Bottom 0.203: v54.86,33.02 54.23,32.38 48.64,32.38 48.13,31.88 48.13,21.59 46.48,19.94 36.32,19.94 34.42,18.03 v31.5,18.03
PA7/D29  (via drill 0.3)
  Top 0.203: U1.71 26.23,12.51 27.81,14.1 28.96,14.1 30.86,16 v30.86,17.4 | v54.86,32.13 55.24,31.75 55.24,29.84 D22~.8
  Bottom 0.203: v54.86,32.13 54.61,31.88 48.9,31.88 48.51,31.5 48.51,21.34 46.74,19.56 36.45,19.56 34.29,17.4 v30.86,17.4
PB0/D53  (via drill 0.3)
  Top 0.203: D46~.8 58.17,9.14 58.17,13.21 57.66,13.72 55.88,13.72 51.05,18.54 v50.55,18.54 | U1.19 38.81,19.51 37.59,18.29 v37.59,17.78
  Bottom 0.203: v37.59,17.78 37.85,18.03 47.75,18.03 48.26,18.54 v50.55,18.54
PB1/SCK/D52  (via drill 0.3)
  Top 0.203: D46~.7 58.67,11.18 58.67,13.46 57.91,14.22 56.01,14.22 50.8,19.43 v50.55,19.43 49.53,20.45 49.53,21.84 50.55,22.86 50.55,26.92 ISP.2 | U1.20 38.74,20.01 36.96,18.23 v36.96,17.14
  Bottom 0.203: v36.96,17.14 36.96,18.06 37.32,18.41 47.5,18.41 48.51,19.43 v50.55,19.43
PB2/MOSI/D51  (via drill 0.3)
  Top 0.203: 59.69,13.08 D46~.6 59.69,13.21 58.42,14.48 58.42,15.75 57.91,16.26 54.61,16.26 v50.55,20.32 49.91,20.95 49.91,21.59 51.05,22.73 51.05,26.92 ISP.5 | U1.21 38.67,20.51 36.32,18.16 v36.32,17.78
  Bottom 0.203: v36.32,17.78 36.32,17.98 37.13,18.8 47.24,18.8 48.77,20.32 v50.55,20.32
PB3/MISO/D50  (via drill 0.3)
  Top 0.203: D46~.5 58.17,16.76 54.74,16.76 51.18,20.32 51.18,20.57 v50.55,21.21 53.34,24 53.34,28.45 52.58,29.21 50.8,29.21 ISP.1 | U1.22 38.6,21.01 35.69,18.1 v35.69,17.14
  Bottom 0.203: v35.69,17.14 35.69,18.1 36.77,19.18 46.99,19.18 49.02,21.21 v50.55,21.21
PB4/D10  (via drill 0.3)
  Top 0.203: U1.23 40.81,21.51 41.4,22.1 41.4,22.99 39.24,25.15 39.24,33.02 40.77,34.54 v40.77,36.58
  Bottom 0.203: 8~1.3 24.64,45.21 39.12,45.21 40.77,43.56 v40.77,36.58
  Bottom 0.406: 8~13.3 22.61,49.28 8~1.3
PB5/D11  (via drill 0.3)
  Top 0.203: U1.24 40.81,22.01 41.02,22.23 41.02,22.73 38.86,24.89 38.86,33.27 40.13,34.54 v40.13,35.94
  Bottom 0.203: 8~1.4 22.48,44.83 38.48,44.83 40.13,43.18 v40.13,35.94
  Bottom 0.406: 8~13.4 20.07,49.28 8~1.4
PB6/D12  (via drill 0.3)
  Top 0.203: U1.25 38.83,22.51 38.48,22.86 38.48,33.53 39.5,34.54 v39.5,36.58
  Bottom 0.203: 8~1.5 20.32,44.45 37.85,44.45 39.5,42.8 v39.5,36.58
  Bottom 0.406: 8~13.5 17.53,49.28 8~1.5
PB7/D13  (via drill 0.3)
  Top 0.203: v28.83,43.81 R9.1 | U1.26 37.75,27.97 38.1,28.32 38.1,33.78 38.86,34.54 v38.86,35.94
  Bottom 0.203: 8~1.6 18.16,44.07 28.83,44.07 | 28.83,44.07 28.19,44.07 | 28.83,44.07 28.32,44.07 | 28.83,44.07 v28.83,43.81 28.83,43.69 | 28.83,44.07 29.46,44.07 | v38.86,35.94 38.86,42.42 37.21,44.07 28.83,44.07
  Bottom 0.406: 8~13.6 14.99,49.28 8~1.6
PC0/D37  (via drill 0.3)
  Top 0.203: D30~.8 56.13,8.64 56.13,10.41 55.24,11.3 48.26,11.3 46.86,9.91 v45.85,9.91 | U1.53 25.57,21.51 25.65,21.59 v28.45,21.59
  Bottom 0.203: v28.45,21.59 27.51,21.59 23.5,17.57 23.5,13.72 26.16,11.05 32.13,11.05 32.51,10.67 42.8,10.67 43.56,9.91 v45.85,9.91
PC1/D36  (via drill 0.3)
  Top 0.203: D30~.7 55.63,11.68 47.62,11.68 v46.48,10.54 | U1.54 25.6,21.01 25.65,20.95 v27.81,20.95
  Bottom 0.203: v27.81,20.95 27.56,20.95 23.88,17.27 23.88,13.84 26.29,11.43 32.26,11.43 32.64,11.05 43.05,11.05 43.56,10.54 v46.48,10.54
PC2/D35  (via drill 0.3)
  Top 0.203: D30~.6 56.52,12.06 46.74,12.06 v45.85,11.18 | U1.55 25.46,20.51 25.65,20.32 v28.45,20.32
  Bottom 0.203: v28.45,20.32 27.56,20.32 24.26,17.02 24.26,13.97 26.42,11.81 32.38,11.81 32.77,11.43 45.59,11.43 v45.85,11.18
PC3/D34  (via drill 0.3)
  Top 0.203: U1.56 25.33,20.01 25.65,19.68 v27.81,19.68
  Bottom 0.203: D30~.5 53.72,11.81 32.89,11.81 32.51,12.19 26.54,12.19 24.64,14.1 24.64,16.76 27.56,19.68 v27.81,19.68
PC4/D33  (via drill 0.3)
  Top 0.203: U1.57 25.19,19.51 25.65,19.05 v28.45,19.05
  Bottom 0.203: D30~.4 56.13,16.76 56.13,15.03 53.29,12.19 33.02,12.19 32.64,12.57 26.67,12.57 25.02,14.22 25.02,16.51 27.56,19.05 v28.45,19.05
PC5/D32  (via drill 0.3)
  Top 0.203: U1.58 25.06,19.01 25.65,18.41 v27.81,18.41
  Bottom 0.203: D30~.3 55.75,18.92 55.75,15.27 53.06,12.57 33.15,12.57 32.77,12.95 26.8,12.95 25.4,14.35 25.4,16.26 27.56,18.41 v27.81,18.41
PC6/D31  (via drill 0.3)
  Top 0.203: U1.59 24.92,18.51 25.65,17.78 v28.45,17.78
  Bottom 0.203: D30~.2 56.09,22.86 54.61,21.38 54.61,16 52.32,13.72 33.53,13.72 33.15,14.1 28,14.1 26.8,15.3 26.8,17.02 27.56,17.78 v28.45,17.78
PC7/D30  (via drill 0.3)
  Top 0.203: U1.60 24.79,18.01 25.65,17.14 v27.81,17.14
  Bottom 0.203: D30~.1 57.15,24.64 54.23,21.72 54.23,16.26 52.07,14.1 33.66,14.1 33.27,14.48 28.19,14.48 27.18,15.49 27.18,16.51 v27.81,17.14
PD0/SCL  (via drill 0.3)
  Top 0.203: U1.43 29.25,25.57 33.53,29.84 33.53,38.48 35.81,40.77 38.86,40.77 40.13,42.04 50.42,42.04 51.51,40.94 52.63,40.94 53.72,42.04 v53.72,42.93 | I2C.3 69.34,7.11 69.34,27.05 v68.2,28.19
  Bottom 0.203: v68.2,28.19 66.29,30.1 66.29,46.45 65.75,46.99 55.88,46.99 53.72,44.83 v53.72,42.93
PD1/SDA  (via drill 0.3)
  Top 0.203: U1.44 28.75,25.57 33.15,29.97 33.15,38.73 35.56,41.15 38.23,41.15 39.5,42.42 50.67,42.42 51.59,41.51 52.3,41.51 v53.09,42.29 | I2C.4 67.31,4.45 69.72,6.86 69.72,27.56 v68.2,29.08
  Bottom 0.203: v68.2,29.08 66.8,30.48 66.8,46.61 66.04,47.37 55.63,47.37 53.09,44.83 v53.09,42.29
PD2/RX1  (via drill 0.3)
  Top 0.203: U1.45 28.25,25.58 32.77,30.1 32.77,38.99 35.31,41.53 37.59,41.53 38.86,42.8 51.31,42.8 v51.82,42.29
  Bottom 0.203: v51.82,42.29 51.82,43.31 52.32,43.81 52.32,51.18 53.59,52.45 65.66,52.45 SERIAL.1
PD3/TX1  (via drill 0.3)
  Top 0.203: U1.46 27.75,25.59 32.38,30.23 32.38,39.24 35.05,41.91 37.08,41.91 38.35,43.18 52.2,43.18 v52.45,42.93
  Bottom 0.203: v52.45,42.93 52.7,43.18 52.7,50.93 53.85,52.07 63.5,52.07 SERIAL.2
PD4
  Top 0.203: U1.47 27.25,25.6 32,30.35 32,41.21 35.88,45.09 55.88,45.09 56.26,44.7 57.66,44.7 58.67,43.69 58.67,42.67 59.18,42.16 65.66,42.16 66.8,41.02 66.8,26.92 66.04,26.16 66.04,25.78 65.66,25.4 J8.1
PD5
  Top 0.203: U1.48 26.75,25.61 31.62,30.48 31.62,41.4 35.69,45.47 54.36,45.47 55.88,46.99 57.91,46.99 58.29,46.61 58.29,44.65 58.75,44.2 65.53,44.2 67.18,42.55 67.18,27.69 68.58,26.29 68.58,24.64 68.07,24.13 66.04,24.13 J8.2
PD6
  Top 0.203: U1.49 26.25,25.61 31.24,30.61 31.24,41.6 35.49,45.85 54.1,45.85 55.63,47.37 58.17,47.37 58.67,46.86 58.67,44.83 58.93,44.58 65.79,44.58 67.56,42.8 67.56,27.94 68.96,26.54 68.96,22.35 68.2,21.59 66.04,21.59 J8.3
PD7/D38
  Top 0.203: U1.50 25.75,25.62 30.86,30.73 30.86,41.83 35.26,46.23 53.85,46.23 55.37,47.75 58.42,47.75 59.69,46.48 D38~.1
PE0/RX0/D0  (via drill 0.3)
  Top 0.203: 0~1.1 47.88,46.61 29.34,46.61 28.19,45.47 26.16,45.47 24.26,43.56 R1.2 | U1.2 42.08,11.01 48.13,17.06 48.13,35.81 v46.74,37.21
  Bottom 0.203: 0~1.1 46.48,45.21 46.48,37.47 v46.74,37.21
  Bottom 0.406: 0~1.1 0~7.1
PE1/TX0/D1  (via drill 0.3)
  Top 0.203: 0~1.2 45.72,46.99 29.08,46.99 27.94,45.85 23.75,45.85 21.46,43.56 R2.2 | U1.3 41.98,11.51 47.75,17.28 47.75,34.92 v46.1,36.58
  Bottom 0.203: 0~1.2 46.86,48.26 46.86,48.13 45.85,47.12 45.85,36.83 v46.1,36.58
  Bottom 0.406: 0~1.2 0~7.2
PE2
  Top 0.203: U1.4 38.68,12.01 38.35,11.68 38.35,10.41 38.86,9.91 41.02,9.91 45.59,5.33 62.48,5.33 J8.8
PE3/D5  (via drill 0.3)
  Top 0.203: U1.5 42.4,12.51 47.37,17.48 47.37,34.16 v45.21,36.32
  Top 0.406: 0~1.6 0~7.6
  Bottom 0.203: 0~1.6 38.1,49.53 45.21,49.53 45.72,49.02 45.72,47.75 45.21,47.24 v45.21,36.32
PE4/D2  (via drill 0.3)
  Top 0.203: U1.6 42.35,13.01 46.99,17.65 46.99,33.4 v44.96,35.43
  Top 0.406: 0~1.3 0~7.3
  Bottom 0.203: v44.96,35.43 44.58,35.81 44.58,48.13 0~1.3
PE5/D3  (via drill 0.3)
  Top 0.203: U1.7 42.27,13.51 46.61,17.85 46.61,32.51 v44.45,34.67
  Top 0.406: 0~1.4 0~7.4
  Bottom 0.203: v44.45,34.67 43.94,35.18 43.94,45.47 41.91,47.5 0~1.4
PE6
  Top 0.203: U1.8 38.52,14.01 37.97,13.46 37.97,10.29 38.73,9.53 40.89,9.53 45.47,4.95 63.63,4.95 65.79,7.11 65.79,9.14 J8.7
PE7
  Top 0.203: U1.9 38.39,14.51 37.59,13.72 37.59,10.16 38.61,9.14 40.77,9.14 45.34,4.57 63.88,4.57 66.17,6.86 66.17,11.3 J8.6
PF0/D54
  Top 0.203: U1.97 36.25,3.12 0~2.1
PF1/D55
  Top 0.203: U1.96 35.75,1.46 35.94,1.27 38.1,1.27 0~2.2
PF2/D56
  Top 0.203: 0~2.3 40.26,0.89 35.69,0.89 35.31,1.27 35.31,4.06 35.25,4.12 U1.95
PF3/D57
  Top 0.203: 0~2.4 42.42,0.51 35.43,0.51 34.92,1.02 34.92,3.81 34.75,3.98 U1.94
PF4/D58  (via drill 0.3)
  Top 0.203: U1.93 34.25,3.47 v34.29,3.43
  Bottom 0.203: 0~2.5 45.85,3.68 34.54,3.68 v34.29,3.43
PF5/D59  (via drill 0.3)
  Top 0.203: U1.92 33.75,3.9 33.66,3.81 33.66,3.17 v34.29,2.54
  Bottom 0.203: 0~2.6 48.26,1.27 35.56,1.27 v34.29,2.54
PF6/D60  (via drill 0.3)
  Top 0.203: U1.91 33.25,2.69 v34.29,1.65
  Bottom 0.203: 0~2.7 50.42,0.89 35.05,0.89 v34.29,1.65
PF7/D61  (via drill 0.3)
  Top 0.203: U1.90 32.75,4.05 v32.64,3.94
  Bottom 0.203: 0~2.8 52.58,0.51 34.29,0.51 33.02,1.78 33.02,3.56 v32.64,3.94
PG0/D41  (via drill 0.3)
  Top 0.203: U1.51 21.62,22.51 v21.59,22.48 | v36.07,42.55 36.96,42.55 37.97,43.56 53.98,43.56 54.61,42.93 54.61,40.99 55.98,39.62 58.17,39.62 D38~.4
  Bottom 0.203: v36.07,42.55 35.31,43.31 29.97,43.31 29.46,42.8 28.19,42.8 27.69,43.31 15.11,43.31 14.61,42.8 14.61,24 16.13,22.48 v21.59,22.48
PG1/D40  (via drill 0.3)
  Top 0.203: U1.52 22.39,22.01 v22.23,21.84 | v36.07,43.43 36.96,44.32 54.48,44.32 56.64,42.16 58.04,42.16 59.56,40.64 D38~.3
  Bottom 0.203: v36.07,43.43 35.81,43.69 29.72,43.69 29.21,43.18 28.45,43.18 27.94,43.69 14.99,43.69 14.22,42.93 14.22,23.75 16.13,21.84 v22.23,21.84
PG2/D39  (via drill 0.3)
  Top 0.203: U1.70 26.22,13.01 27.69,14.48 28.7,14.48 30.23,16 30.23,18.03 v30.86,18.67
  Bottom 0.203: D38~.2 58.42,44.45 56.64,44.45 55.63,43.43 55.63,42.42 54.23,41.02 52.15,41.02 45.85,34.72 45.85,23.11 44.96,22.23 34.42,22.23 v30.86,18.67
PG3  (via drill 0.3)
  Top 0.203: J8.5 62.99,17.02 62.99,26.29 63.63,26.92 65.41,26.92 66.04,27.56 66.04,38.48 65.15,39.37 59.31,39.37 58.42,40.26 58.42,41.15 57.91,41.66 56.52,41.66 54.23,43.94 37.47,43.94 v36.96,43.43 | U1.28 36.75,27.48 37.72,28.45 37.72,34.04 38.23,34.54 v38.23,36.58
  Bottom 0.203: v38.23,36.58 38.23,42.16 v36.96,43.43
PG4  (via drill 0.3)
  Top 0.203: J8.4 63.37,19.18 63.37,26.04 63.75,26.42 65.53,26.42 66.42,27.3 66.42,40.77 65.53,41.66 59.11,41.66 58.29,42.47 58.29,43.46 57.55,44.2 56.13,44.2 55.63,44.7 36.07,44.7 35.18,43.81 v35.18,42.55 | U1.29 36.25,27.49 37.34,28.57 37.34,34.29 37.59,34.54 v37.59,35.94
  Bottom 0.203: v35.18,42.55 35.81,41.91 37.08,41.91 37.59,41.4 v37.59,35.94
PG5/D4  (via drill 0.3)
  Top 0.203: U1.1 42.17,10.51 48.51,16.86 48.51,36.7 v47.37,37.85
  Top 0.406: 0~7.5 0~1.5
  Bottom 0.203: 0~7.5 40.64,52.07 50.55,52.07 51.05,51.56 51.05,47.24 47.12,43.31 47.12,38.1 v47.37,37.85
PH0/RXD2  (via drill 0.3)
  Top 0.203: U1.12 41.28,16.01 v41.91,16.64 | v62.23,45.72 SERIAL.3
  Bottom 0.203: v41.91,16.64 50.8,16.64 51.94,17.78 51.94,22.48 53.98,24.51 53.98,29.72 56.26,32 60.71,32 61.47,32.77 61.47,44.96 v62.23,45.72
PH1/TXD2  (via drill 0.3)
  Top 0.203: U1.13 40.89,16.51 v41.02,16.64 | v61.34,45.72 61.34,49.15 SERIAL.4
  Bottom 0.203: v41.02,16.64 41.66,17.27 50.8,17.27 51.56,18.03 51.56,22.61 53.59,24.64 53.59,29.97 56.13,32.51 56.13,33.66 56.77,34.29 60.33,34.29 61.09,35.05 61.09,45.47 v61.34,45.72
PH2  (via drill 0.3)
  Top 0.203: U1.14 38.73,17.01 38.35,16.64 v38.35,16.26
  Bottom 0.203: J10.1 61.85,42.8 61.85,32.56 60.78,31.5 56.39,31.5 54.36,29.46 54.36,24.38 52.32,22.35 52.32,17.53 50.8,16 38.61,16 v38.35,16.26
PH3/D6  (via drill 0.3)
  Top 0.203: U1.15 41.13,17.51 42.16,18.54 42.16,20.45 42.93,21.21 42.93,23.62 43.18,23.88 45.34,23.88 45.85,24.38 45.85,31.75 43.31,34.29 v43.31,36.58
  Bottom 0.203: 0~1.7 35.81,46.74 41.66,46.74 43.31,45.09 v43.31,36.58
  Bottom 0.406: 0~1.7 0~7.7
PH4/D7  (via drill 0.3)
  Top 0.203: U1.16 41,18.01 41.78,18.8 41.78,20.7 42.55,21.46 42.55,23.88 42.93,24.26 45.09,24.26 45.47,24.64 45.47,31.5 42.67,34.29 v42.67,35.94
  Bottom 0.203: 0~1.8 33.66,46.35 41.02,46.35 42.67,44.7 v42.67,35.94
  Bottom 0.406: 0~1.8 0~7.8
PH5/D8  (via drill 0.3)
  Top 0.203: U1.17 40.86,18.51 41.4,19.05 41.4,20.95 42.16,21.72 42.16,23.5 40.01,25.65 40.01,32.51 42.04,34.54 v42.04,36.58
  Bottom 0.203: 8~1.1 28.96,45.97 40.39,45.97 42.04,44.32 v42.04,36.58
  Bottom 0.406: 8~13.1 27.69,49.28 8~1.1
PH6/D9  (via drill 0.3)
  Top 0.203: U1.18 40.73,19.01 41.02,19.3 41.02,21.21 41.78,21.97 41.78,23.24 39.62,25.4 39.62,32.77 41.4,34.54 v41.4,35.94
  Bottom 0.203: 8~1.2 26.8,45.59 39.75,45.59 41.4,43.94 v41.4,35.94
  Bottom 0.406: 8~13.2 25.15,49.28 8~1.2
PH7  (via drill 0.3)
  Top 0.203: U1.27 37.25,20.23 34.92,17.91 34.92,16.89 35.94,15.88 v37.47,15.88
  Bottom 0.203: J10.2 62.23,40.64 62.23,30.99 60.71,29.46 55.88,29.46 54.74,28.32 54.74,24.26 52.7,22.23 52.7,17.27 51.05,15.62 37.72,15.62 v37.47,15.88
PJ0/RXD3  (via drill 0.3)
  Top 0.203: U1.63 22.73,16.51 22.35,16.13 v21.46,16.13 | v14.22,44.96 14.22,46.23 14.61,46.61 27.43,46.61 29.72,48.9 29.72,51.44 30.73,52.45 55.5,52.45 SERIAL.5
  Bottom 0.203: v21.46,16.13 21.21,16.13 13.84,23.5 13.84,44.58 v14.22,44.96
PJ1/TXD3  (via drill 0.3)
  Top 0.203: U1.64 22.87,16.01 22.1,15.24 v21.46,15.24 | v14.86,45.72 15.37,46.23 27.69,46.23 30.1,48.64 30.1,51.18 30.99,52.07 53.34,52.07 SERIAL.6
  Bottom 0.203: v21.46,15.24 13.46,23.24 13.46,45.21 13.97,45.72 v14.86,45.72
PJ2  (via drill 0.3)
  Top 0.203: U1.65 24.65,15.51 25.65,16.51 v28.45,16.51
  Bottom 0.203: J10.3 62.61,38.48 62.61,30.74 60.83,28.96 56.01,28.96 55.12,28.07 55.12,24.13 53.09,22.1 53.09,17.02 51.31,15.24 34.04,15.24 33.66,15.62 29.59,15.62 28.7,16.51 v28.45,16.51
PJ3  (via drill 0.3)
  Top 0.203: U1.66 24.66,15.01 25.65,16 27.69,16 v27.81,15.88
  Bottom 0.203: J10.4 62.99,36.32 62.99,29.72 60.2,26.92 56.01,26.92 55.5,26.42 55.5,24 53.47,21.97 53.47,16.76 51.56,14.86 33.91,14.86 33.53,15.24 29.34,15.24 28.7,15.88 v27.81,15.88
PJ4  (via drill 0.3)
  Top 0.203: U1.67 24.67,14.51 25.78,15.62 27.18,15.62 27.56,15.24 v28.45,15.24
  Bottom 0.203: J10.5 63.37,34.16 63.37,29.46 60.33,26.42 56.13,26.42 55.88,26.16 55.88,23.88 53.85,21.84 53.85,16.51 51.82,14.48 33.78,14.48 33.4,14.86 28.83,14.86 v28.45,15.24
PJ5  (via drill 0.3)
  Top 0.203: U1.68 25.06,14.01 v26.04,14.99
  Bottom 0.203: J10.6 63.75,32 63.75,29.21 60.96,26.42 60.96,22.48 60.33,21.84 55.88,21.84 54.99,20.95 54.99,15.75 52.58,13.34 33.4,13.34 33.02,13.72 27.81,13.72 26.54,14.99 v26.04,14.99
PJ6  (via drill 0.3)
  Top 0.203: U1.69 25.7,13.51 v26.42,14.22
  Bottom 0.203: J10.7 64.77,29.59 61.47,26.29 61.47,22.35 60.45,21.34 56.01,21.34 55.37,20.7 55.37,15.49 52.83,12.95 33.27,12.95 32.89,13.34 27.3,13.34 v26.42,14.22
PJ7  (via drill 0.3)
  Top 0.203: U1.79 27.25,9.34 28.96,11.05 30.35,11.05 v30.99,10.41 | J10.8 64.01,27.94 62.61,26.54 62.61,7.75 61.21,6.35 56.64,6.35 55.75,7.24 55.75,10.03 54.86,10.92 48.77,10.92 v47.12,9.27
  Bottom 0.203: v30.99,10.41 31.62,9.78 32.13,9.78 32.26,9.91 42.29,9.91 43.31,8.89 46.74,8.89 v47.12,9.27
PL0/D49
  Top 0.203: U1.35 33.25,25.5 36.58,28.83 36.58,36.45 37.85,37.72 43.94,37.72 45.21,38.99 48.39,38.99 49.53,37.85 49.53,33.4 51.31,31.62 52.68,31.62 53.72,30.58 53.72,21.21 55.88,19.05 58.42,19.05 D46~.4
PL1/D48
  Top 0.203: U1.36 32.75,25.51 36.2,28.96 36.2,36.7 37.59,38.1 43.31,38.1 44.58,39.37 48.64,39.37 49.91,38.1 49.91,33.53 51.44,32 52.88,32 54.1,30.78 54.1,23.37 55.88,21.59 58.42,21.59 D46~.3
PL2/D47
  Top 0.203: U1.37 32.25,25.52 35.81,29.08 35.81,36.96 37.34,38.48 42.67,38.48 43.94,39.75 48.9,39.75 50.29,38.35 50.29,33.66 51.56,32.38 53.08,32.38 54.48,30.98 54.48,25.53 55.88,24.13 58.42,24.13 D46~.2
PL3/D46
  Top 0.203: U1.38 31.75,25.53 35.43,29.21 35.43,37.21 37.08,38.86 42.04,38.86 43.31,40.13 49.15,40.13 50.67,38.61 50.67,33.78 51.69,32.77 53.28,32.77 54.86,31.18 54.86,27.69 55.88,26.67 58.42,26.67 D46~.1
PL4/D45
  Top 0.203: U1.39 31.25,25.54 35.05,29.34 35.05,37.47 36.83,39.24 41.4,39.24 42.67,40.51 49.4,40.51 50.67,39.24 53.47,39.24 55.88,36.83 55.88,34.92 56.52,34.29 57.63,34.29 58.17,33.75 58.17,29.46 D38~.8
PL5/D44
  Top 0.203: U1.40 30.75,25.54 34.67,29.46 34.67,37.72 36.58,39.62 40.77,39.62 42.04,40.89 49.66,40.89 50.93,39.62 53.65,39.62 56.57,36.7 57.53,36.7 58.17,36.07 58.17,34.54 58.67,34.04 58.67,31.5 D38~.7
PL6/D43
  Top 0.203: U1.41 30.25,25.55 34.29,29.59 34.29,37.97 36.32,40.01 40.13,40.01 41.4,41.27 49.91,41.27 51.18,40.01 53.82,40.01 56.74,37.08 57.76,37.08 58.67,36.17 58.67,34.8 59.69,33.78 D38~.6
PL7/D42
  Top 0.203: U1.42 29.75,25.56 33.91,29.72 33.91,38.23 36.07,40.39 39.5,40.39 40.77,41.66 50.16,41.66 51.44,40.39 53.98,40.39 55.24,39.12 57.91,39.12 58.42,38.61 58.42,37.08 59.69,35.81 D38~.5
RESET_1280  (via drill 0.3)
  Top 0.203: R6.1 v20.32,7.87 | U1.30 35.75,23.3 32.13,19.68 v29.21,19.68
  Top 0.305: J11.6 18.29,1.78 12.45,1.78 RESET.P$2
  Top 0.406: C1.1 14.61,8.76 15.37,9.53 17.65,9.53 18.41,8.76 RST.2 | RST.2 R6.1 | RST.2 18.41,3.17 J11.6
  Bottom 0.203: ISP.3 50.8,26.67 52.58,26.67 53.21,26.04 53.21,24.77 51.18,22.73 51.18,18.29 50.55,17.65 38.35,17.65 36.32,15.62 34.29,15.62 33.91,16 30.35,16 29.21,17.14 v29.21,19.68 29.21,21.84 28.83,22.23 27.56,22.23 23.11,17.78 23.11,10.67 v20.32,7.87
RI  (via drill 0.3)
  Top 0.305: U2.6 21.3,36.11 v21.46,35.94
  Bottom 0.203: v21.46,35.94 26.54,30.86 39.62,30.86 41.27,29.21 43.18,29.21 UART.5
RTS  (via drill 0.3)
  Top 0.305: U2.3 23.25,36.58 v22.61,35.94
  Bottom 0.203: v22.61,35.94 27.3,31.24 41.15,31.24 UART.1
V_IN
  Top 0.813: J11.1 29.97,0.76 10.03,0.76 D1.+ | D1.+ 6.99,2.29 JST.+ | D1.+ 8.51,3.81 10.79,6.1 C11.+
V_JST
  Top 0.813: EXT_PWR_USB.COM1 7.11,16.13 11.3,16.13 U6.2
VCC_LOG  (via drill 0.3)
  Top 0.203: 43.69,37.34 38.1,37.34 36.96,36.2 36.96,28.7 35.25,27 U1.31 | 43.81,37.34 43.69,37.34 | 43.43,37.34 43.18,37.34 | 43.69,37.34 43.43,37.34 | 43.81,37.34 44.2,37.34 | 43.43,37.34 43.56,37.34 | 43.81,37.34 43.43,37.34 | 44.32,37.08 44.32,36.07 43.81,35.56 43.81,34.42 46.23,32 46.23,18.16 44.58,16.51 C5.2 | 44.32,37.08 44.07,37.34 43.81,37.34 | 43.81,37.34 44.32,37.34 44.32,37.08 | 44.32,37.08 44.58,37.34 43.81,37.34 | 35.25,24.19 35.31,24.13
  Top 0.305: 21.21,17.53 20.32,18.41 | 21.23,17.51 20.34,17.51 20.32,17.53 | 20.32,16.76 20.45,16.76 21.21,17.53 | 21.21,17.53 20.95,17.53 | 20.95,17.53 20.83,17.53 20.32,17.02 20.32,18.03 20.45,18.03 20.95,17.53 | 21.23,17.51 U1.61 | 21.21,17.53 21.23,17.51 | 20.32,13.84 20.32,14.61 19.56,13.84 | 20.32,13.84 19.56,13.84 | 20.32,13.84 20.32,13.08 | 20.32,13.08 20.32,12.83 | 19.56,13.84 20.32,13.08 | 19.56,13.84 R7.1 | U1.80 27.75,7.43 26.16,5.84 24.89,5.84 | 24.13,5.84 24.13,6.6 | 24.13,6.6 24.13,6.73 | 24.13,6.6 24.89,5.84 | 24.13,5.84 24.89,5.84 | 24.13,5.84 24.13,5.08 | 24.13,5.08 24.13,4.83 | 24.89,5.84 24.13,5.08 | C3.2 18.41,23.88 18.8,23.5 24.26,23.5 25.27,22.48 30.1,22.48 | 30.1,22.48 34.16,22.48 35.25,23.57 35.25,24.19 | v34.67,16.26 35.92,15.01 U1.10 42.7,15.01 43.56,15.88 C5.2 | 30.1,22.48 29.59,22.48 | 29.59,22.48 29.34,22.48 | 29.59,22.48 30.1,21.97 | 30.1,22.48 30.1,21.97 | 30.1,22.48 30.61,22.48 | 30.61,22.48 30.73,22.48 | 30.1,21.97 30.61,22.48 | 30.1,21.97 v30.1,21.34 | ISP.6 51.82,30.48 49.02,33.27 49.02,37.59 48.06,38.56 45.8,38.56 44.58,37.34
  Top 0.762: U3.3 14.22,25.4 15.24,24.38 C4.1 17.53,24.38 17.65,24.51 C3.2
  Top 0.813: C12.+ C4.1 | C12.+ 14.99,22.73 14.86,22.86 F1.2 11.94,22.86 11.3,23.5 3V3_VCC_5V.B | J11.4 24.13,5.84 24.13,6.86 20.57,10.41 R6.2 20.32,13.84 20.32,16.76 20.32,17.02 20.32,17.53 20.32,18.03 20.32,18.41 20.32,20.57 18.16,22.73 C12.+
  Bottom 0.305: v34.67,16.26 34.29,16.64 30.61,16.64 30.1,17.14 v30.1,21.34
  pour Top: -7.62,50.16 -5.08,50.16 -5.08,48.26 -7.62,48.26
VCC_SW  (via drill 0.3)
  Top 0.203: U1.100 37.75,8.1 37.85,8
  Top 0.305: I2C.1 58.17,4.06 45.21,4.06 40.77,8.51 U1.100 | v38.23,6.6 38.23,7.62 37.85,8
  Top 0.406: 3V3_VCC_5V.COM 4.19,26.54 2.01,24.37 2.01,19.96 2.54,19.43 9.4,19.43 11.05,17.78 13.97,17.78 16.26,15.49 C13.1 R8.1 v15.62,13.84
  Top 0.813: C2.2 17.65,15.62 17.53,15.49 C13.1
  Bottom 0.406: v38.23,6.6 38.1,6.48 35.18,6.48 34.67,6.99 16.89,6.99 15.62,8.26 v15.62,13.84
VDD5_USB  (via drill 0.51 pad 1.02)
  Top 0.203: 25.4,32.38 29.54,32.38 29.72,32.56 29.72,34.8 29.46,35.05 R5.1
  Top 0.305: 25.4,32.38 24.26,33.53 19.68,33.53 19.34,33.19 U2.20 | R5.1 28.7,35.05 R3.2 R4.2 26.04,38.48 25.53,38.99 25.53,41.53 25.02,42.04 22.86,42.04 | C8.+ 17.4,43.43 19.05,43.43 20.45,42.04 22.86,42.04 | 7.37,42.67 J1.VDD | U2.4 22.59,40.25 22.86,40.51 22.86,41.53 | 23.37,42.04 22.86,41.53 | 23.37,42.04 23.62,42.04 | 22.86,42.04 23.37,42.04 | 22.86,42.04 22.86,41.53 | 22.86,41.53 22.35,42.04 | 22.35,42.04 22.23,42.04 | 22.86,42.04 22.35,42.04
  Top 0.813: 6.35,42.67 7.37,42.67 v8.89,42.67 C10.2 C7.1 15.37,42.67 C8.+
  Bottom 0.813: EXT_PWR_USB.CH2B 0.76,28.07 0.76,37.08 6.35,42.67 v8.89,42.67

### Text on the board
Top: top layer
Bottom: bottom layer
Dimension: boardoutline
tPlace: 14 | 15 | 16 | 17 | 18 | 19 | TX3 | RX3 | TX2 | RX2 | TX1 | RX1 | silktop | AREF | GND | 1 | 1 | 1 | 1 | 9 | 8 | 7 | 6 | 5 | 4 | 3 | 2 | 1 | 0 | 3 | 2 | 1 | 0 | 22 | 38 | PH2 | PWM | TX0 | RX0 | 23 | 39 | PH7 | Seeeduino Mega | 24 | 40 | PJ2 | v1.1 06/24/2009 | 25 | 41 | PJ3 | ANALOG IN | 26 | 42 | PJ4 | by Seeed Studio | Partner w/ NKC electronics | 27 | 43 | PJ5 | RTS | DTR | 28 | 44 | PJ6 | DSR | RI | 29 | 45 | PJ7 | CTS | DCD | 30 | 46 | PD4 | 8 | 31 | 47 | PD5 | 9 | 32 | 48 | PD6 | 10 | 33 | 49 | PG4 | 11 | 34 | 50 | 12 | PG3 | 35 | 51 | PE7 | 13 | 36 | 52 | 14 | PE6 | AREF | 37 | 53 | PE2 | 15 | POWER | ANALOG IN | RST | 3V3 | 5V | GND | Vin | 0 | 1 | 2 | 3 | 4 | 5 | 6 | 7 | VCC | GND | SCL | SDA | 21 | 20
bPlace: 14 | 15 | 16 | 17 | 18 | 19 | silkbottom | TX3 | RX3 | TX2 | RX2 | TX1 | RX1 | SERIAL | AREF | GND | 22 | PH2 | 1 | 1 | 1 | 1 | 9 | 8 | 7 | 6 | 5 | 4 | 3 | 2 | 1 | TX0 | 0 | RX0 | 38 | 3 | 2 | 1 | 0 | 23 | PH7 | PWM | 24 | 39 | PJ2 | 40 | Electronics can be art | 25 | PJ3 | ANALOG IN | 26 | 41 | PJ4 | 42 | 27 | PJ5 | seeedstudio.com | 1 | 43 | PJ6 | CC | DTR | 28 | A_RST_M | RTS | 44 | 29 | PJ7 | RI | DSR | 45 | PD4 | DCD | 30 | 8 | 5V_VCC_3V3 | CTS | 46 | 31 | PD5 | 9 | 47 | PD6 | 32 | 10 | USB_PWR_EXT | 33 | 48 | PG4 | 11 | 49 | PG3 | 34 | 12 | 35 | 50 | PE7 | 13 | 51 | 36 | PE6 | 14 | 37 | 52 | PE2 | 15 | 53 | - | RST | 3V3 | 5V | GND | Vin | 0 | 1 | 2 | 3 | 4 | 5 | 6 | 7 | VCC | GND | SCL | SDA | + | 21 | 20
tStop: ~soldermask top
bStop: ~soldermask bottom
tCream: ~padmask top
bCream: ~padmask bottom
Drills: drill
Reference: SUPER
